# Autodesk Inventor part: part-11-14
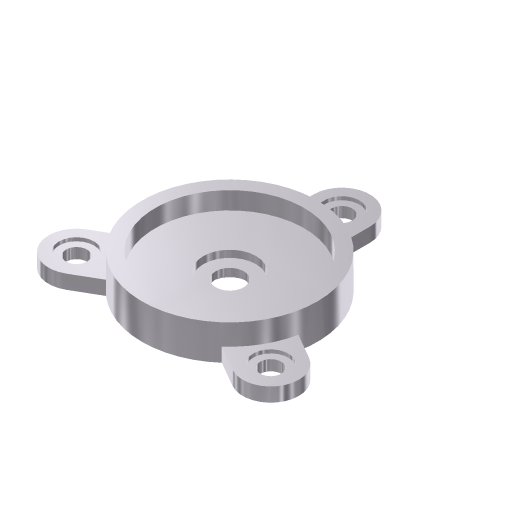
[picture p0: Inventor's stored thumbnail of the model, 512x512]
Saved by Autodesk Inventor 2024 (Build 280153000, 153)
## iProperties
Company: CADCIM Technologies
Shininess: 64.0
Length Units: 11269
Angle Units: 11279
Time Units: 11290
Mass Units: 11283
Length Display Precision: 3
Angle Display Precision: 2
Compacted: True
Part Number: part-11-14
Document SubType Name: Modeling
Created: 2002-12
Designer: deepak
Description: Sample Drawing
Engineer: Deepak
Vendor: CADSoft
Density: 1 g/cm^3
Material: Generic
Appearance: Metal-AL-6061 (Polished)
Density: 0.0
Volumn: 0.0
Area: 0.0
PropertySet Name: Model Information
Control State: 0
Master: False
Checked Out: False
Title: Aligned Section
Author: deepak
Revision Number: 4
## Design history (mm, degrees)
revolve "Revolution1" stored, may be unused: angle "d6" = 90 deg
sketch "Sketch3"
  geometry: C1 r 21.25 at (0, 0) reference
hole "Hole1" sketch "Sketch3" diameter "d7" = 8; stored, may be unused: countersink angle "d11" = 82 deg, drill point angle "d13" = 118 deg; dims "d8" = 6, "d9" = 15, "d10" = 2, "d12" = 8
sketch "Sketch4"
  geometry: L1 (8, 23.685)-(8, 32); L2 (-8, 32)-(-8, 23.685); C1 r 5 at (0, 0) reference; C2 r 25 at (0, 0) reference; A1 r 8 centre (0, 32) between (8, 32) and (-8, 32); A2 r 25 centre (0, 0) between (8, 23.685) and (-8, 23.685)
  constraints: 4 end point, 4 point on circle, 2 centre point, 2 concentric, 2 tangent, 2 vertical, 1 parallel
  dimensions: "d14" = 8 radius of A1; "d15" = 32 distance of C1.centre A1.centre
extrude "Extrusion1" join sketch "Sketch4" distance "d16" = 4; taper "d17" = 0 deg
sketch "Sketch5"
  geometry: A1 r 8 centre (0, 32) between (8, 32) and (-8, 32) reference
hole "Hole2" sketch "Sketch5" diameter "d18" = 6; stored, may be unused: countersink angle "d22" = 82 deg, drill point angle "d24" = 118 deg; dims "d19" = 6, "d20" = 10, "d21" = 1, "d23" = 8
pattern_circular "Circular Pattern1" dims angle "d27" = 360 deg
body "Solid1"
node "Sketch1"
sketch "Sketch2"
  geometry: L1 (0, 1)-(0, 5); L2 (0, 5)-(-21.25, 5); L3 (-21.25, 5)-(-21.25, 10); L4 (-21.25, 10)-(-25, 10); L5 (-25, 10)-(-25, 0); L6 (-25, 0)-(-5, 0); L7 (0, 1)-(-5, 1); L8 (-5, 1)-(-5, 0); 1 further point
  constraints: 16 end point, 3 parallel, 3 perpendicular, 1 horizontal, 1 horizontal alignment, 1 vertical, 1 vertical alignment, 1 other
  dimensions: "d0" = 50 diameter of L5 L1; "d1" = 10 diameter of L8 L1; "d2" = 42.5 diameter of L3 L1; "d3" = 10 distance of L4.end L5.end; "d4" = 1 distance of L7.end L6.end; "d5" = 4 distance of L1.start L1.end
